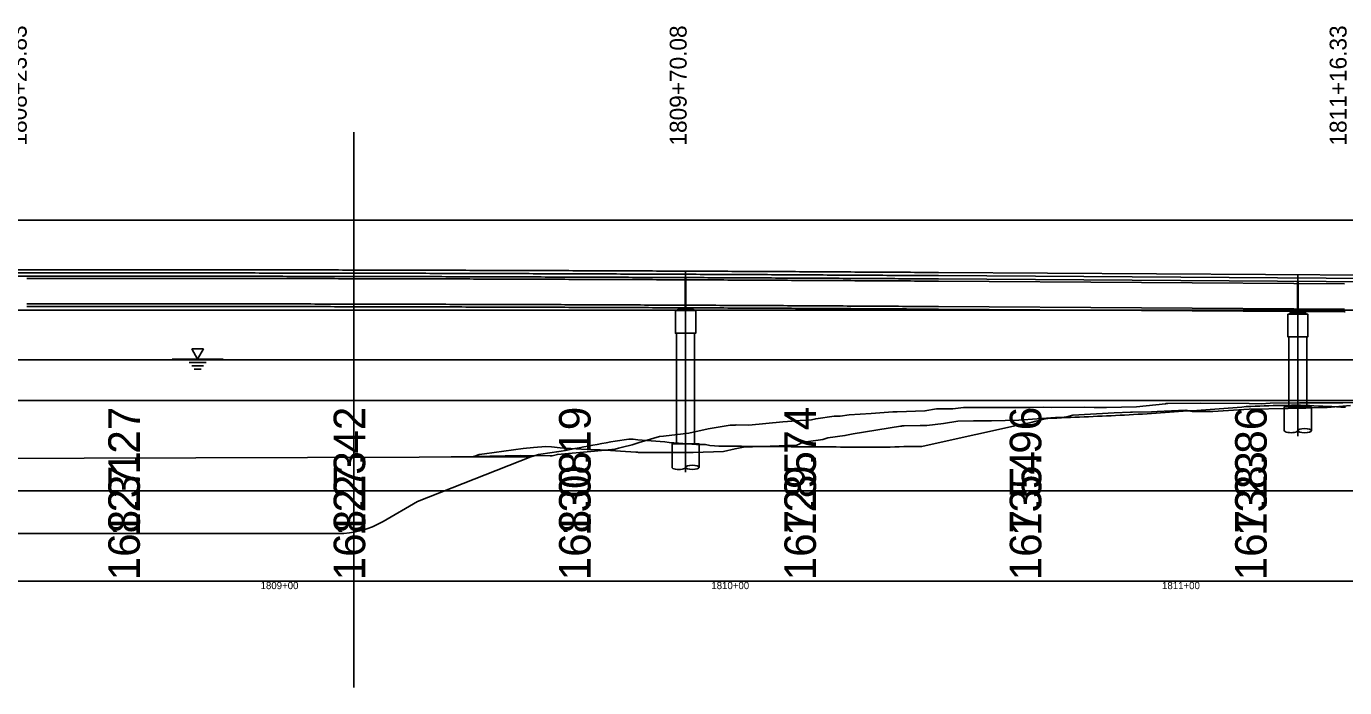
# Model space of a CAD drawing. Extents: x 2126510 to 2136144, y 865066 to 868066.
# Drawn here: x 2133446.8 to 2133739.3, y 867790.7 to 867937.3 of the extents above; entities that cross this region are included whole.
import ezdxf

# ---------------------------------------------------------------- set-up
doc = ezdxf.new("R2010")
doc.units = 0
for name, color, linetype in [('RD_DTM_BkLn1', 7, 'Continuous'), ('RD_EX_BldgApp', 7, 'Continuous'), ('RD_EX_Bridge', 7, 'Continuous'), ('RD_EX_Conc_Curb', 7, 'Continuous'), ('RD_EX_GuardRail', 7, 'Continuous'), ('RD_EX_H2O', 7, 'Continuous'), ('RD_EX_Misc', 7, 'Continuous'), ('RD_EX_Misc_Golf_Cartpath', 7, 'Continuous'), ('RD_EX_UT', 7, 'Continuous'), ('RD_HC_Data', 7, 'Continuous'), ('RD_HC_txCode', 7, 'Continuous')]:
    doc.layers.add(name, color=color, linetype=linetype)

msp = doc.modelspace()

# ---------------------------------------------------------------- linework, layer by layer
at = {"layer": 'RD_DTM_BkLn1'}
for p, q in [((2133649.16, 867881.28), (2134230.74, 867877.62)), ((2133594.82, 867874.58), (2133591.32, 867874.58)), ((2133591.32, 867874.58), (2133591.32, 867874.25)), ((2133591.74, 867874.58), (2133594.4, 867874.58)), ((2133594.82, 867874.25), (2133594.82, 867874.58)), ((2133730.66, 867873.78), (2133727.16, 867873.78)), ((2133727.16, 867873.78), (2133727.16, 867873.45)), ((2133727.57, 867873.78), (2133730.24, 867873.78)), ((2133730.66, 867873.45), (2133730.66, 867873.78)), ((2133591.07, 867869.25), (2133591.07, 867844.75)), ((2133595.07, 867869.25), (2133595.07, 867844.75)), ((2133726.91, 867868.45), (2133726.91, 867852.91)), ((2133730.91, 867868.45), (2133730.91, 867852.91))]:
    msp.add_line(p, q, dxfattribs=at)
for points in [[(2133590.82, 867874.25), (2133595.32, 867874.25), (2133595.32, 867869.25), (2133590.82, 867869.25)], [(2133726.66, 867873.45), (2133731.16, 867873.45), (2133731.16, 867868.45), (2133726.66, 867868.45)]]:
    msp.add_lwpolyline(points, close=True, dxfattribs=at)
for points in [[(2133725.91, 867847.66), (2133725.91, 867852.91), (2133731.91, 867852.91), (2133731.91, 867847.66)], [(2133590.07, 867839.51), (2133590.07, 867844.75), (2133596.07, 867844.75), (2133596.07, 867839.51)]]:
    msp.add_lwpolyline(points, dxfattribs=at)
for centre in [(2133727.41, 867847.66), (2133591.57, 867839.51)]:
    msp.add_ellipse(centre, major_axis=(-1.5, 0), ratio=0.310397, start_param=0, end_param=3.141593, dxfattribs=at)
for centre in [(2133730.41, 867847.66), (2133594.57, 867839.51)]:
    msp.add_ellipse(centre, major_axis=(-1.5, 0), ratio=0.310397, dxfattribs=at)
msp.add_spline([(2133296.65, 867881.51), (2133303.7, 867881.54), (2133310.75, 867881.58), (2133317.8, 867881.61), (2133324.85, 867881.64), (2133331.9, 867881.67), (2133338.95, 867881.69), (2133346, 867881.72), (2133353.05, 867881.74), (2133360.1, 867881.76), (2133367.15, 867881.78), (2133374.2, 867881.8), (2133381.25, 867881.82), (2133388.3, 867881.83), (2133395.35, 867881.85), (2133402.4, 867881.86), (2133409.45, 867881.87), (2133416.5, 867881.88), (2133423.55, 867881.89), (2133430.6, 867881.89), (2133437.65, 867881.9), (2133444.7, 867881.9), (2133451.76, 867881.9), (2133458.81, 867881.9), (2133465.86, 867881.9), (2133472.91, 867881.89), (2133479.96, 867881.89), (2133487.01, 867881.88), (2133494.06, 867881.87), (2133501.11, 867881.86), (2133508.16, 867881.85), (2133515.21, 867881.84), (2133522.26, 867881.82), (2133529.31, 867881.8), (2133536.36, 867881.79), (2133543.41, 867881.77), (2133550.46, 867881.75), (2133557.51, 867881.72), (2133564.56, 867881.7), (2133571.61, 867881.67), (2133578.66, 867881.64), (2133585.71, 867881.62), (2133592.76, 867881.58), (2133599.81, 867881.55), (2133606.86, 867881.52), (2133613.91, 867881.48), (2133620.96, 867881.45), (2133628.01, 867881.41), (2133635.06, 867881.37), (2133642.11, 867881.32), (2133649.16, 867881.28)], degree=3, dxfattribs=at)
at = {"layer": 'RD_EX_BldgApp'}
for p, q in [((2133483.51, 867865.79), (2133486.13, 867865.79)), ((2133484.82, 867863.51), (2133483.51, 867865.79)), ((2133486.13, 867865.79), (2133484.82, 867863.51)), ((2133479.2, 867863.51), (2133490.45, 867863.51)), ((2133482.95, 867862.76), (2133486.7, 867862.76)), ((2133483.51, 867862.01), (2133486.13, 867862.01)), ((2133484.07, 867861.26), (2133485.57, 867861.26))]:
    msp.add_line(p, q, dxfattribs=at)
at = {"layer": 'RD_EX_Bridge'}
for p, q in [((2133591.74, 867874.88), (2133591.74, 867874.58)), ((2133592.74, 867874.88), (2133592.74, 867874.58)), ((2133593.4, 867874.58), (2133593.4, 867874.88)), ((2133594.4, 867874.58), (2133594.4, 867874.88)), ((2133727.57, 867874.07), (2133727.57, 867873.78)), ((2133728.57, 867874.07), (2133728.57, 867873.78)), ((2133729.24, 867873.78), (2133729.24, 867874.07)), ((2133730.24, 867873.78), (2133730.24, 867874.07))]:
    msp.add_line(p, q, dxfattribs=at)
at = {"layer": 'RD_EX_Conc_Curb'}
msp.add_lwpolyline([(2133545.92, 867841.84), (2133547.29, 867842.33), (2133548.44, 867842.49), (2133557.07, 867843.72), (2133559.33, 867843.88), (2133562.1, 867844.12), (2133563.32, 867844.05), (2133565.23, 867843.82), (2133569.96, 867843.58), (2133574.14, 867843.39), (2133582.01, 867842.87), (2133582.43, 867842.86), (2133582.6, 867842.84), (2133590.67, 867842.83), (2133592.39, 867842.82), (2133594.63, 867842.82), (2133594.76, 867842.82), (2133601.47, 867843.05), (2133604.05, 867843.65), (2133605.9, 867843.98), (2133617.73, 867844.46), (2133618.45, 867844.7), (2133618.62, 867844.9), (2133619.83, 867845.17), (2133623.54, 867845.71), (2133624.67, 867846.06), (2133628.42, 867846.57), (2133630.29, 867846.91), (2133640.77, 867848.65), (2133640.96, 867848.67), (2133641.15, 867848.7), (2133641.54, 867848.71), (2133645.12, 867848.81), (2133646.63, 867848.76), (2133650.27, 867849.2), (2133653.48, 867849.77), (2133656.94, 867849.82), (2133660.92, 867849.81), (2133667.04, 867849.97), (2133675.11, 867850.6), (2133677.08, 867850.61), (2133677.69, 867850.75), (2133678.99, 867851.05), (2133688.15, 867851.61), (2133691.76, 867851.78), (2133692.21, 867851.76), (2133696.42, 867851.83), (2133697.69, 867851.9), (2133702.42, 867852.12), (2133702.64, 867852.09), (2133704.07, 867852.22), (2133705.47, 867851.88), (2133710.06, 867851.93), (2133718.09, 867852.43), (2133726.79, 867852.56), (2133730.66, 867852.65), (2133733.54, 867852.81), (2133735.45, 867852.81), (2133740.63, 867853.26)], dxfattribs=at)
at = {"layer": 'RD_EX_GuardRail'}
for p, q in [((2135251.98, 867894.32), (2130671.73, 867894.32)), ((2135251.98, 867874.32), (2133154.4, 867874.32)), ((2135251.98, 867854.32), (2130671.73, 867854.32)), ((2135251.98, 867834.32), (2130671.73, 867834.32)), ((2135251.98, 867814.32), (2130671.73, 867814.32))]:
    msp.add_line(p, q, dxfattribs=at)
at = {"layer": 'RD_EX_H2O'}
msp.add_line((2133197.59, 867824.82), (2133515.91, 867824.82), dxfattribs=at)
for points in [[(2133686.47, 867850.93), (2133687.47, 867850.97), (2133688.47, 867851.02), (2133689.47, 867851.06), (2133690.47, 867851.11), (2133691.47, 867851.15), (2133692.47, 867851.21), (2133693.47, 867851.28), (2133694.47, 867851.34), (2133695.47, 867851.41), (2133696.47, 867851.48), (2133697.47, 867851.54), (2133698.47, 867851.61), (2133699.47, 867851.68), (2133700.47, 867851.74), (2133701.47, 867851.81), (2133702.47, 867851.88), (2133703.47, 867851.95), (2133704.47, 867852.01), (2133705.47, 867852.08), (2133706.47, 867852.15), (2133707.47, 867852.21), (2133708.47, 867852.28), (2133709.47, 867852.35), (2133710.47, 867852.41), (2133711.47, 867852.48), (2133712.47, 867852.55), (2133713.47, 867852.61), (2133714.47, 867852.68), (2133715.47, 867852.78), (2133716.47, 867852.88), (2133717.47, 867852.97), (2133718.47, 867853.02), (2133719.47, 867853.06), (2133720.47, 867853.09), (2133721.47, 867853.12), (2133722.47, 867853.16), (2133723.47, 867853.19), (2133724.47, 867853.22), (2133725.47, 867853.24), (2133726.47, 867853.26), (2133727.47, 867853.29), (2133728.47, 867853.31), (2133729.47, 867853.28), (2133730.47, 867853.24), (2133731.47, 867853.19), (2133732.47, 867853.15), (2133733.47, 867853.1), (2133734.47, 867853.06), (2133735.47, 867853.01), (2133736.47, 867852.97), (2133737.47, 867852.92), (2133738.47, 867852.88), (2133739.47, 867852.83)], [(2133586.47, 867845.31), (2133587.47, 867845.23), (2133588.47, 867845.14), (2133589.47, 867845.06), (2133590.47, 867844.97), (2133591.47, 867844.89), (2133592.47, 867844.81), (2133593.47, 867844.72), (2133594.47, 867844.64), (2133595.47, 867844.58), (2133596.47, 867844.58), (2133597.47, 867844.59), (2133598.47, 867844.39), (2133599.47, 867844.26), (2133600.47, 867844.24), (2133601.47, 867844.23), (2133602.47, 867844.21), (2133603.47, 867844.19), (2133604.47, 867844.18), (2133605.47, 867844.18), (2133606.47, 867844.17), (2133607.47, 867844.16), (2133608.47, 867844.15), (2133609.47, 867844.15), (2133610.47, 867844.14), (2133611.47, 867844.13), (2133612.47, 867844.13), (2133613.47, 867844.12), (2133614.47, 867844.11), (2133615.47, 867844.11), (2133616.47, 867844.1), (2133617.47, 867844.09), (2133618.47, 867844.08), (2133619.47, 867844.08), (2133620.47, 867844.07), (2133621.47, 867844.06), (2133622.47, 867844.06), (2133623.47, 867844.05), (2133624.47, 867844.04), (2133625.47, 867844.04), (2133626.47, 867844.03), (2133627.47, 867844.02), (2133628.47, 867844.01), (2133629.47, 867844.01), (2133630.47, 867844), (2133631.47, 867843.99), (2133632.47, 867843.99), (2133633.47, 867843.98), (2133634.47, 867843.97), (2133635.47, 867843.97), (2133636.47, 867843.96), (2133637.47, 867843.97), (2133638.47, 867844), (2133639.47, 867844.04), (2133640.47, 867844.08), (2133641.47, 867844.12), (2133642.47, 867844.15), (2133643.47, 867844.13), (2133644.47, 867844.12), (2133645.47, 867844.13), (2133646.47, 867844.35), (2133647.47, 867844.57), (2133648.47, 867844.79), (2133649.47, 867845.01), (2133650.47, 867845.24), (2133651.47, 867845.46), (2133652.47, 867845.68), (2133653.47, 867845.9), (2133654.47, 867846.12), (2133655.47, 867846.34), (2133656.47, 867846.56), (2133657.47, 867846.78), (2133658.47, 867847), (2133659.47, 867847.22), (2133660.47, 867847.44), (2133661.47, 867847.66), (2133662.47, 867847.88), (2133663.47, 867848.1), (2133664.47, 867848.32), (2133665.47, 867848.54), (2133666.47, 867848.76), (2133667.47, 867848.98), (2133668.47, 867849.2), (2133669.47, 867849.42), (2133670.47, 867849.68), (2133671.47, 867849.93), (2133672.47, 867850.19), (2133673.47, 867850.35), (2133674.47, 867850.4), (2133675.47, 867850.44), (2133676.47, 867850.49), (2133677.47, 867850.53), (2133678.47, 867850.58), (2133679.47, 867850.62), (2133680.47, 867850.66), (2133681.47, 867850.71), (2133682.47, 867850.75), (2133683.47, 867850.8), (2133684.47, 867850.84), (2133685.47, 867850.88), (2133686.47, 867850.93)], [(2133558.75, 867841.84), (2133559.47, 867842.08), (2133560.47, 867842.36), (2133561.47, 867842.5), (2133562.47, 867842.64), (2133563.47, 867842.78), (2133564.47, 867842.92), (2133565.47, 867843.1), (2133566.47, 867843.28), (2133567.47, 867843.47), (2133568.47, 867843.66), (2133569.47, 867843.84), (2133570.47, 867844.03), (2133571.47, 867844.22), (2133572.47, 867844.41), (2133573.47, 867844.59), (2133574.47, 867844.78), (2133575.47, 867844.97), (2133576.47, 867845.16), (2133577.47, 867845.31), (2133578.47, 867845.46), (2133579.47, 867845.6), (2133580.47, 867845.75), (2133581.47, 867845.74), (2133582.47, 867845.65), (2133583.47, 867845.57), (2133584.47, 867845.48), (2133585.47, 867845.4), (2133586.47, 867845.31)], [(2133558.75, 867841.84), (2133533.6, 867831.97), (2133525.97, 867827.53)]]:
    msp.add_lwpolyline(points, dxfattribs=at)
msp.add_arc((2133515.91, 867844.82), 20, 270, 300.189, dxfattribs=at)
at = {"layer": 'RD_EX_Misc'}
for p, q in [((2133519.44, 867913.84), (2133519.44, 867790.7)), ((2133649.16, 867882.7), (2134667.76, 867876.29)), ((2131523, 867814.32), (2135677.25, 867814.32))]:
    msp.add_line(p, q, dxfattribs=at)
for points in [[(2131430.13, 867814.32), (2131430.13, 867863.32), (2136143.96, 867863.32)], [(2133162.33, 867840.65), (2133558.75, 867841.84)]]:
    msp.add_lwpolyline(points, dxfattribs=at)
msp.add_spline([(2133296.65, 867882.93), (2133303.7, 867882.97), (2133310.75, 867883), (2133317.8, 867883.03), (2133324.85, 867883.06), (2133331.9, 867883.09), (2133338.95, 867883.12), (2133346, 867883.14), (2133353.05, 867883.16), (2133360.1, 867883.19), (2133367.15, 867883.21), (2133374.2, 867883.23), (2133381.25, 867883.24), (2133388.3, 867883.26), (2133395.35, 867883.27), (2133402.4, 867883.28), (2133409.45, 867883.29), (2133416.5, 867883.3), (2133423.55, 867883.31), (2133430.6, 867883.32), (2133437.65, 867883.32), (2133444.7, 867883.32), (2133451.76, 867883.32), (2133458.81, 867883.32), (2133465.86, 867883.32), (2133472.91, 867883.32), (2133479.96, 867883.31), (2133487.01, 867883.3), (2133494.06, 867883.3), (2133501.11, 867883.29), (2133508.16, 867883.27), (2133515.21, 867883.26), (2133522.26, 867883.25), (2133529.31, 867883.23), (2133536.36, 867883.21), (2133543.41, 867883.19), (2133550.46, 867883.17), (2133557.51, 867883.15), (2133564.56, 867883.12), (2133571.61, 867883.1), (2133578.66, 867883.07), (2133585.71, 867883.04), (2133592.76, 867883.01), (2133599.81, 867882.98), (2133606.86, 867882.94), (2133613.91, 867882.91), (2133620.96, 867882.87), (2133628.01, 867882.83), (2133635.06, 867882.79), (2133642.11, 867882.75), (2133649.16, 867882.7)], degree=3, dxfattribs=at)
at = {"layer": 'RD_EX_Misc_Golf_Cartpath'}
msp.add_lwpolyline([(2133541.04, 867841.84), (2133542.23, 867841.84), (2133549.67, 867842), (2133556.36, 867842.13), (2133563, 867842.05), (2133563.02, 867842.05), (2133563.44, 867842.05), (2133564.64, 867842.37), (2133572.89, 867843.12), (2133577.42, 867843.54), (2133578.17, 867843.77), (2133579.07, 867843.97), (2133581.21, 867844.53), (2133582.78, 867845), (2133587.28, 867846.38), (2133588.16, 867846.41), (2133593.82, 867847.11), (2133598.09, 867848.04), (2133602.96, 867848.83), (2133604.06, 867848.88), (2133604.29, 867848.92), (2133607.12, 867848.89), (2133614.65, 867849.63), (2133617.71, 867849.85), (2133618.48, 867849.9), (2133620.98, 867850.08), (2133621.96, 867850.27), (2133626.02, 867850.85), (2133627.37, 867850.83), (2133629.35, 867851.14), (2133634.22, 867851.47), (2133639.06, 867851.81), (2133639.36, 867851.81), (2133639.64, 867851.82), (2133640.05, 867851.84), (2133646.18, 867852.01), (2133648.73, 867852.48), (2133652.37, 867852.48), (2133654.75, 867852.81), (2133657.72, 867852.76), (2133659.05, 867852.76), (2133662.72, 867852.78), (2133666.7, 867852.81), (2133669.51, 867852.81), (2133672.49, 867852.83), (2133674.36, 867852.81), (2133681.55, 867852.82), (2133683.76, 867852.81), (2133686.44, 867852.81), (2133693.15, 867852.92), (2133699.53, 867853.62), (2133699.73, 867853.64), (2133700.07, 867853.65), (2133707.34, 867853.71), (2133718.11, 867853.69), (2133720.75, 867853.62), (2133722.77, 867853.74), (2133729.27, 867853.81), (2133734.19, 867853.82), (2133736.13, 867853.81), (2133738.91, 867853.82), (2133743.7, 867853.86)], dxfattribs=at)
at = {"layer": 'RD_EX_UT'}
msp.add_line((2133649.16, 867882.01), (2134667.76, 867875.59), dxfattribs=at)
msp.add_spline([(2133296.65, 867882.24), (2133303.7, 867882.27), (2133310.75, 867882.3), (2133317.8, 867882.34), (2133324.85, 867882.37), (2133331.9, 867882.39), (2133338.95, 867882.42), (2133346, 867882.45), (2133353.05, 867882.47), (2133360.1, 867882.49), (2133367.15, 867882.51), (2133374.2, 867882.53), (2133381.25, 867882.55), (2133388.3, 867882.56), (2133395.35, 867882.57), (2133402.4, 867882.59), (2133409.45, 867882.6), (2133416.5, 867882.61), (2133423.55, 867882.61), (2133430.6, 867882.62), (2133437.65, 867882.62), (2133444.7, 867882.63), (2133451.76, 867882.63), (2133458.81, 867882.63), (2133465.86, 867882.62), (2133472.91, 867882.62), (2133479.96, 867882.62), (2133487.01, 867882.61), (2133494.06, 867882.6), (2133501.11, 867882.59), (2133508.16, 867882.58), (2133515.21, 867882.56), (2133522.26, 867882.55), (2133529.31, 867882.53), (2133536.36, 867882.52), (2133543.41, 867882.5), (2133550.46, 867882.47), (2133557.51, 867882.45), (2133564.56, 867882.43), (2133571.61, 867882.4), (2133578.66, 867882.37), (2133585.71, 867882.34), (2133592.76, 867882.31), (2133599.81, 867882.28), (2133606.86, 867882.25), (2133613.91, 867882.21), (2133620.96, 867882.17), (2133628.01, 867882.13), (2133635.06, 867882.09), (2133642.11, 867882.05), (2133649.16, 867882.01)], degree=3, dxfattribs=at)
at = {"layer": 'RD_HC_Data'}
for p, q in [((2133593.07, 867883.06), (2133593.07, 867838.47)), ((2133728.91, 867882.2), (2133728.91, 867846.42)), ((2133739.24, 867874.01), (2133739.4, 867874.01))]:
    msp.add_line(p, q, dxfattribs=at)
at = {"layer": 'RD_HC_txCode'}
for p, q in [((2133592.99, 867881.58), (2133592.99, 867874.88)), ((2133593.15, 867881.58), (2133593.15, 867874.88)), ((2133649.16, 867880.78), (2133739.24, 867880.21)), ((2133728.82, 867880.78), (2133728.82, 867874.07)), ((2133728.99, 867880.78), (2133728.99, 867874.07)), ((2133649.16, 867875.16), (2133739.24, 867874.59)), ((2133649.16, 867874.57), (2133739.24, 867874.01))]:
    msp.add_line(p, q, dxfattribs=at)
for points in [[(2133446.9, 867881.4), (2133451.76, 867881.4), (2133458.81, 867881.4), (2133465.86, 867881.4), (2133472.91, 867881.39), (2133479.96, 867881.39), (2133487.01, 867881.38), (2133494.06, 867881.37), (2133501.11, 867881.36), (2133508.16, 867881.35), (2133515.21, 867881.34), (2133522.26, 867881.32), (2133529.31, 867881.31), (2133536.36, 867881.29), (2133543.41, 867881.27), (2133550.46, 867881.25), (2133557.51, 867881.22), (2133564.56, 867881.2), (2133571.61, 867881.17), (2133578.66, 867881.15), (2133585.71, 867881.12), (2133592.76, 867881.09), (2133592.99, 867881.09)], [(2133593.15, 867881.08), (2133599.81, 867881.05), (2133606.86, 867881.02), (2133613.91, 867880.98), (2133620.96, 867880.95), (2133628.01, 867880.91), (2133635.06, 867880.87), (2133642.11, 867880.83), (2133649.16, 867880.78)], [(2133446.9, 867875.78), (2133451.76, 867875.78), (2133458.81, 867875.78), (2133465.86, 867875.77), (2133472.91, 867875.77), (2133479.96, 867875.76), (2133487.01, 867875.76), (2133494.06, 867875.75), (2133501.11, 867875.74), (2133508.16, 867875.73), (2133515.21, 867875.71), (2133522.26, 867875.7), (2133529.31, 867875.68), (2133536.36, 867875.66), (2133543.41, 867875.64), (2133550.46, 867875.62), (2133557.51, 867875.6), (2133564.56, 867875.58), (2133571.61, 867875.55), (2133578.66, 867875.52), (2133585.71, 867875.49), (2133592.76, 867875.46), (2133592.99, 867875.46)], [(2133446.9, 867875.19), (2133451.76, 867875.19), (2133458.81, 867875.19), (2133465.86, 867875.19), (2133472.91, 867875.19), (2133479.96, 867875.18), (2133487.01, 867875.17), (2133494.06, 867875.17), (2133501.11, 867875.15), (2133508.16, 867875.14), (2133515.21, 867875.13), (2133522.26, 867875.11), (2133529.31, 867875.1), (2133536.36, 867875.08), (2133543.41, 867875.06), (2133550.46, 867875.04), (2133557.51, 867875.02), (2133564.56, 867874.99), (2133571.61, 867874.97), (2133578.66, 867874.94), (2133585.71, 867874.91), (2133592.76, 867874.88), (2133592.99, 867874.88)], [(2133593.15, 867875.46), (2133599.81, 867875.43), (2133606.86, 867875.39), (2133613.91, 867875.36), (2133620.96, 867875.32), (2133628.01, 867875.28), (2133635.06, 867875.24), (2133642.11, 867875.2), (2133649.16, 867875.16)], [(2133593.15, 867874.88), (2133599.81, 867874.85), (2133606.86, 867874.81), (2133613.91, 867874.78), (2133620.96, 867874.74), (2133628.01, 867874.7), (2133635.06, 867874.66), (2133642.11, 867874.62), (2133649.16, 867874.57)]]:
    msp.add_spline(points, degree=3, dxfattribs=at)

# ---------------------------------------------------------------- texts
at = {"layer": 'RD_EX_Misc'}
for s, height, p in [('1808+23.83', 3.75, (2133446.89, 867910.84)), ('1809+70.08', 3.75, (2133593.31, 867910.84)), ('1811+16.33', 3.75, (2133739.73, 867910.84)), ('127.27', 7, (2133472, 867824.32)), ('127.42', 7, (2133522, 867824.32)), ('130.19', 7, (2133572, 867824.32)), ('129.74', 7, (2133622, 867824.32)), ('135.96', 7, (2133672, 867824.32)), ('138.86', 7, (2133722, 867824.32)), ('168.31', 7, (2133472, 867814.47)), ('168.23', 7, (2133522, 867814.47)), ('168.08', 7, (2133572, 867814.47)), ('167.85', 7, (2133622, 867814.47)), ('167.54', 7, (2133672, 867814.47)), ('167.23', 7, (2133722, 867814.47))]:
    msp.add_text(s, height=height, rotation=90, dxfattribs=at).set_placement(p)
for s, p in [('1809+00', (2133498.79, 867812.52)), ('1810+00', (2133598.79, 867812.52)), ('1811+00', (2133698.79, 867812.52))]:
    msp.add_text(s, height=1.6, dxfattribs=at).set_placement(p)

doc.saveas('drawing.dxf')
